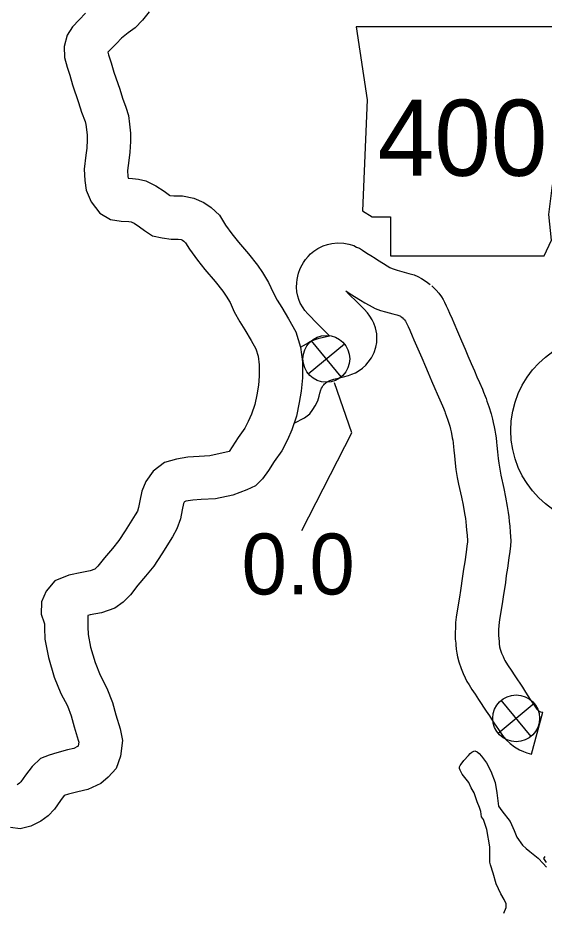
# Model space of a CAD drawing. Extents: x -939622 to -934245, y 1383184 to 1385301.
# Drawn here: x -936319.11 to -936308.16, y 1384751.56 to 1384770.09 of the extents above; entities that cross this region are included whole.
import ezdxf

# ---------------------------------------------------------------- set-up
doc = ezdxf.new("R2010")
doc.units = 0
for name, color, linetype in [('Level 10', 7, 'Continuous'), ('Level 15', 7, 'Continuous'), ('Level 21', 7, 'Continuous'), ('Level 25', 7, 'Continuous'), ('Level 26', 7, 'Continuous'), ('Level 27', 7, 'Continuous'), ('Level 9', 7, 'Continuous')]:
    doc.layers.add(name, color=color, linetype=linetype)

msp = doc.modelspace()

# ---------------------------------------------------------------- linework, layer by layer
at = {"layer": 'Level 10'}
for points in [[(-936313.228, 1384763.232), (-936313.105, 1384763.305), (-936313.025, 1384763.348), (-936312.943, 1384763.383), (-936312.839, 1384763.419), (-936312.753, 1384763.441), (-936312.656, 1384763.465), (-936312.629, 1384763.471), (-936312.683, 1384763.525), (-936312.867, 1384763.711), (-936313.078, 1384763.924), (-936313.137, 1384763.996), (-936313.176, 1384764.049), (-936313.234, 1384764.146), (-936313.263, 1384764.222), (-936313.285, 1384764.295), (-936313.305, 1384764.386), (-936313.31, 1384764.483), (-936313.309, 1384764.569), (-936313.299, 1384764.642), (-936313.287, 1384764.709), (-936313.269, 1384764.775), (-936313.238, 1384764.87), (-936313.196, 1384764.948), (-936313.168, 1384764.995), (-936313.128, 1384765.055), (-936313.073, 1384765.122), (-936313.023, 1384765.172), (-936312.952, 1384765.229), (-936312.869, 1384765.287), (-936312.761, 1384765.34), (-936312.671, 1384765.371), (-936312.575, 1384765.391), (-936312.461, 1384765.401), (-936312.331, 1384765.395), (-936312.223, 1384765.375), (-936312.122, 1384765.346), (-936312.061, 1384765.317), (-936312.004, 1384765.29), (-936311.937, 1384765.249), (-936311.848, 1384765.192), (-936311.764, 1384765.138), (-936311.678, 1384765.084), (-936311.625, 1384765.05), (-936311.504, 1384764.974), (-936311.423, 1384764.924), (-936311.373, 1384764.894), (-936311.319, 1384764.867), (-936311.279, 1384764.853), (-936311.216, 1384764.834), (-936311.073, 1384764.796), (-936310.974, 1384764.769), (-936310.867, 1384764.735), (-936310.788, 1384764.702), (-936310.714, 1384764.665), (-936310.653, 1384764.628), (-936310.584, 1384764.58), (-936310.53, 1384764.537)], [(-936310.5, 1384764.51), (-936310.457, 1384764.469), (-936310.409, 1384764.419), (-936310.353, 1384764.355), (-936310.299, 1384764.278), (-936310.263, 1384764.222), (-936310.234, 1384764.17), (-936310.195, 1384764.091), (-936310.165, 1384764.025), (-936310.129, 1384763.941), (-936310.077, 1384763.82), (-936310.042, 1384763.737), (-936309.964, 1384763.556), (-936309.882, 1384763.368), (-936309.804, 1384763.189), (-936309.745, 1384763.052), (-936309.678, 1384762.892), (-936309.609, 1384762.738), (-936309.557, 1384762.619), (-936309.505, 1384762.495), (-936309.445, 1384762.359), (-936309.422, 1384762.3), (-936309.386, 1384762.215), (-936309.369, 1384762.162), (-936309.35, 1384762.109), (-936309.313, 1384762.001), (-936309.262, 1384761.849), (-936309.233, 1384761.738), (-936309.218, 1384761.667), (-936309.197, 1384761.577), (-936309.184, 1384761.504), (-936309.17, 1384761.424), (-936309.161, 1384761.344), (-936309.152, 1384761.258), (-936309.144, 1384761.186), (-936309.13, 1384761.055), (-936309.118, 1384760.914), (-936309.106, 1384760.822), (-936309.084, 1384760.692), (-936309.058, 1384760.571), (-936308.999, 1384760.295), (-936308.961, 1384760.111), (-936308.928, 1384759.92), (-936308.909, 1384759.796), (-936308.897, 1384759.706), (-936308.886, 1384759.607), (-936308.876, 1384759.509), (-936308.864, 1384759.383), (-936308.855, 1384759.203), (-936308.86, 1384759.102), (-936308.875, 1384758.979), (-936308.893, 1384758.847), (-936308.922, 1384758.632), (-936308.947, 1384758.479), (-936308.967, 1384758.336), (-936309.014, 1384758.035), (-936309.035, 1384757.889), (-936309.082, 1384757.609), (-936309.097, 1384757.509), (-936309.104, 1384757.435), (-936309.108, 1384757.357), (-936309.112, 1384757.275), (-936309.111, 1384757.226), (-936309.105, 1384757.179), (-936309.098, 1384757.105), (-936309.094, 1384757.041), (-936309.092, 1384757.023), (-936309.087, 1384757.001), (-936309.072, 1384756.947), (-936309.045, 1384756.865), (-936309.015, 1384756.794), (-936308.991, 1384756.738), (-936308.979, 1384756.714), (-936308.959, 1384756.682), (-936308.91, 1384756.604), (-936308.847, 1384756.511), (-936308.771, 1384756.396), (-936308.613, 1384756.157), (-936308.547, 1384756.056), (-936308.497, 1384755.981), (-936308.45, 1384755.905), (-936308.367, 1384755.781), (-936308.312, 1384755.702), (-936308.301, 1384755.689), (-936308.281, 1384755.67), (-936308.273, 1384755.664), (-936308.262, 1384755.657), (-936308.256, 1384755.655), (-936308.252, 1384755.653), (-936308.234, 1384755.648), (-936308.185, 1384755.635)], [(-936313.362, 1384761.654), (-936313.148, 1384761.763), (-936313.037, 1384761.848), (-936312.974, 1384761.934), (-936312.922, 1384762.011), (-936312.872, 1384762.118), (-936312.844, 1384762.216), (-936312.826, 1384762.279), (-936312.804, 1384762.348), (-936312.801, 1384762.356), (-936312.79, 1384762.379), (-936312.774, 1384762.41), (-936312.771, 1384762.414), (-936312.763, 1384762.427), (-936312.747, 1384762.449), (-936312.73, 1384762.467), (-936312.712, 1384762.485), (-936312.701, 1384762.495), (-936312.698, 1384762.497), (-936312.676, 1384762.513), (-936312.662, 1384762.522), (-936312.635, 1384762.536), (-936312.619, 1384762.543), (-936312.58, 1384762.556), (-936312.533, 1384762.568), (-936312.445, 1384762.59), (-936312.337, 1384762.615), (-936312.233, 1384762.643), (-936312.161, 1384762.669), (-936312.086, 1384762.701), (-936312.008, 1384762.748), (-936311.94, 1384762.799), (-936311.872, 1384762.861), (-936311.819, 1384762.919), (-936311.749, 1384763.01), (-936311.694, 1384763.122), (-936311.66, 1384763.233), (-936311.644, 1384763.33), (-936311.64, 1384763.409), (-936311.644, 1384763.512), (-936311.67, 1384763.637), (-936311.707, 1384763.73), (-936311.741, 1384763.8), (-936311.787, 1384763.878), (-936311.837, 1384763.946), (-936311.908, 1384764.024), (-936312.046, 1384764.161), (-936312.228, 1384764.344), (-936312.287, 1384764.404), (-936312.247, 1384764.379), (-936312.16, 1384764.324), (-936312.104, 1384764.288), (-936311.98, 1384764.211), (-936311.892, 1384764.156), (-936311.804, 1384764.104), (-936311.675, 1384764.039), (-936311.563, 1384763.998), (-936311.459, 1384763.968), (-936311.306, 1384763.927), (-936311.228, 1384763.906), (-936311.18, 1384763.89), (-936311.164, 1384763.884), (-936311.147, 1384763.875), (-936311.145, 1384763.874), (-936311.123, 1384763.858), (-936311.092, 1384763.834)], [(-936311.122, 1384763.86), (-936311.094, 1384763.833), (-936311.075, 1384763.814), (-936311.063, 1384763.8), (-936311.046, 1384763.776), (-936311.036, 1384763.759), (-936311.029, 1384763.748), (-936311.007, 1384763.703), (-936310.989, 1384763.664), (-936310.957, 1384763.588), (-936310.905, 1384763.467), (-936310.869, 1384763.383), (-936310.79, 1384763.198), (-936310.707, 1384763.009), (-936310.631, 1384762.834), (-936310.574, 1384762.701), (-936310.504, 1384762.533), (-936310.431, 1384762.372), (-936310.384, 1384762.265), (-936310.332, 1384762.14), (-936310.277, 1384762.014), (-936310.256, 1384761.961), (-936310.229, 1384761.897), (-936310.219, 1384761.866), (-936310.199, 1384761.812), (-936310.166, 1384761.715), (-936310.125, 1384761.592), (-936310.108, 1384761.528), (-936310.096, 1384761.471), (-936310.079, 1384761.398), (-936310.071, 1384761.349), (-936310.061, 1384761.295), (-936310.055, 1384761.243), (-936310.046, 1384761.16), (-936310.039, 1384761.09), (-936310.026, 1384760.971), (-936310.013, 1384760.818), (-936309.996, 1384760.686), (-936309.968, 1384760.523), (-936309.939, 1384760.385), (-936309.88, 1384760.11), (-936309.846, 1384759.942), (-936309.816, 1384759.773), (-936309.799, 1384759.667), (-936309.79, 1384759.596), (-936309.781, 1384759.514), (-936309.772, 1384759.423), (-936309.762, 1384759.318), (-936309.756, 1384759.202), (-936309.757, 1384759.18), (-936309.768, 1384759.093), (-936309.785, 1384758.967), (-936309.812, 1384758.765), (-936309.837, 1384758.613), (-936309.857, 1384758.467), (-936309.903, 1384758.171), (-936309.924, 1384758.03), (-936309.971, 1384757.748), (-936309.99, 1384757.618), (-936310.001, 1384757.502), (-936310.007, 1384757.402), (-936310.012, 1384757.288), (-936310.01, 1384757.16), (-936309.999, 1384757.077), (-936309.995, 1384757.039), (-936309.991, 1384756.952), (-936309.978, 1384756.865), (-936309.963, 1384756.791), (-936309.934, 1384756.685), (-936309.888, 1384756.548), (-936309.844, 1384756.443), (-936309.805, 1384756.354), (-936309.765, 1384756.274), (-936309.723, 1384756.206), (-936309.662, 1384756.109), (-936309.594, 1384756.01), (-936309.523, 1384755.901), (-936309.364, 1384755.662), (-936309.298, 1384755.561), (-936309.254, 1384755.494), (-936309.207, 1384755.418), (-936309.111, 1384755.275), (-936309.029, 1384755.156), (-936308.957, 1384755.07), (-936308.864, 1384754.983), (-936308.776, 1384754.915), (-936308.673, 1384754.855), (-936308.589, 1384754.818), (-936308.522, 1384754.794), (-936308.474, 1384754.781), (-936308.422, 1384754.767), (-936308.185, 1384755.635)]]:
    msp.add_lwpolyline(points, dxfattribs=at)
at = {"layer": 'Level 15'}
for points in [[(-936317.706, 1384770.181), (-936317.838, 1384770.043), (-936317.975, 1384769.902), (-936318.088, 1384769.722), (-936318.147, 1384769.487), (-936318.138, 1384769.263), (-936318.088, 1384769.059), (-936318.03, 1384768.89), (-936317.976, 1384768.69), (-936317.847, 1384768.325), (-936317.788, 1384768.124), (-936317.713, 1384767.932), (-936317.694, 1384767.866), (-936317.679, 1384767.759), (-936317.667, 1384767.646), (-936317.67, 1384767.55), (-936317.678, 1384767.373), (-936317.698, 1384767.23), (-936317.729, 1384766.94), (-936317.718, 1384766.699), (-936317.69, 1384766.499), (-936317.585, 1384766.254), (-936317.405, 1384766.02), (-936317.182, 1384765.89), (-936316.958, 1384765.852), (-936316.802, 1384765.845), (-936316.75, 1384765.839), (-936316.741, 1384765.837), (-936316.688, 1384765.811), (-936316.582, 1384765.739), (-936316.473, 1384765.659), (-936316.307, 1384765.548), (-936316.11, 1384765.505), (-936315.919, 1384765.483), (-936315.774, 1384765.482), (-936315.714, 1384765.471), (-936315.682, 1384765.458), (-936315.656, 1384765.439), (-936315.621, 1384765.407), (-936315.541, 1384765.27), (-936315.371, 1384765.044), (-936315.219, 1384764.849), (-936315.008, 1384764.602), (-936314.847, 1384764.398), (-936314.775, 1384764.296), (-936314.694, 1384764.162), (-936314.608, 1384763.967), (-936314.492, 1384763.759), (-936314.39, 1384763.592), (-936314.257, 1384763.37), (-936314.16, 1384763.196), (-936314.111, 1384763.043), (-936314.089, 1384762.868), (-936314.088, 1384762.631), (-936314.106, 1384762.44), (-936314.141, 1384762.244), (-936314.181, 1384762.037), (-936314.252, 1384761.839), (-936314.316, 1384761.686), (-936314.389, 1384761.546), (-936314.525, 1384761.352), (-936314.711, 1384761.06)], [(-936316.381, 1384770.213), (-936316.519, 1384770.035), (-936316.673, 1384769.877), (-936316.817, 1384769.772), (-936316.952, 1384769.663), (-936317.06, 1384769.554), (-936317.189, 1384769.419), (-936317.237, 1384769.369), (-936317.223, 1384769.313), (-936317.169, 1384769.153), (-936317.116, 1384768.958), (-936316.99, 1384768.601), (-936316.935, 1384768.414), (-936316.861, 1384768.224), (-936316.811, 1384768.056), (-936316.786, 1384767.87), (-936316.765, 1384767.683), (-936316.77, 1384767.515), (-936316.781, 1384767.29), (-936316.804, 1384767.12), (-936316.827, 1384766.912), (-936316.821, 1384766.781), (-936316.816, 1384766.747), (-936316.724, 1384766.742), (-936316.602, 1384766.727), (-936316.449, 1384766.695), (-936316.237, 1384766.592), (-936316.064, 1384766.476), (-936315.956, 1384766.396), (-936315.95, 1384766.392), (-936315.867, 1384766.383), (-936315.688, 1384766.382), (-936315.448, 1384766.337), (-936315.239, 1384766.246), (-936315.09, 1384766.141), (-936314.913, 1384765.978), (-936314.791, 1384765.77), (-936314.656, 1384765.591), (-936314.521, 1384765.418), (-936314.312, 1384765.173), (-936314.126, 1384764.938), (-936314.021, 1384764.79), (-936313.894, 1384764.578), (-936313.801, 1384764.368), (-936313.714, 1384764.212), (-936313.62, 1384764.058), (-936313.478, 1384763.821), (-936313.329, 1384763.555), (-936313.228, 1384763.236), (-936313.189, 1384762.925), (-936313.188, 1384762.592), (-936313.213, 1384762.321), (-936313.256, 1384762.079), (-936313.311, 1384761.798), (-936313.413, 1384761.514), (-936313.5, 1384761.304), (-936313.619, 1384761.076), (-936313.777, 1384760.852), (-936313.894, 1384760.668), (-936314.018, 1384760.491), (-936314.169, 1384760.35)], [(-936314.711, 1384761.06), (-936315.116, 1384760.971), (-936315.34, 1384760.96), (-936315.571, 1384760.947), (-936315.811, 1384760.906), (-936316.059, 1384760.835), (-936316.296, 1384760.656), (-936316.448, 1384760.438), (-936316.528, 1384760.238), (-936316.57, 1384760.033), (-936316.598, 1384759.899), (-936316.624, 1384759.824), (-936316.669, 1384759.744), (-936316.877, 1384759.412), (-936317.007, 1384759.208), (-936317.144, 1384759.043), (-936317.306, 1384758.852), (-936317.446, 1384758.676), (-936317.509, 1384758.612), (-936317.509, 1384758.611), (-936317.605, 1384758.578), (-936317.78, 1384758.545), (-936318.051, 1384758.491), (-936318.338, 1384758.371), (-936318.525, 1384758.155), (-936318.618, 1384757.934), (-936318.623, 1384757.676), (-936318.562, 1384757.496), (-936318.555, 1384757.474), (-936318.554, 1384757.392), (-936318.547, 1384757.155), (-936318.475, 1384756.776), (-936318.352, 1384756.368), (-936318.213, 1384756.03), (-936318.081, 1384755.77), (-936318.001, 1384755.559), (-936317.938, 1384755.331), (-936317.854, 1384755.057), (-936317.843, 1384755.012), (-936317.854, 1384754.936), (-936317.855, 1384754.933), (-936317.856, 1384754.932), (-936317.869, 1384754.921), (-936317.949, 1384754.884), (-936318.08, 1384754.852), (-936318.303, 1384754.795), (-936318.459, 1384754.746), (-936318.638, 1384754.677), (-936318.813, 1384754.509), (-936318.954, 1384754.326), (-936319.048, 1384754.187), (-936319.074, 1384754.161), (-936319.105, 1384754.138), (-936319.124, 1384754.128)], [(-936314.169, 1384760.35), (-936314.346, 1384760.266), (-936314.637, 1384760.155), (-936314.997, 1384760.075), (-936315.293, 1384760.061), (-936315.469, 1384760.051), (-936315.612, 1384760.027), (-936315.643, 1384760.018), (-936315.651, 1384760.006), (-936315.663, 1384759.977), (-936315.689, 1384759.851), (-936315.728, 1384759.66), (-936315.8, 1384759.452), (-936315.896, 1384759.284), (-936316.116, 1384758.932), (-936316.279, 1384758.676), (-936316.454, 1384758.465), (-936316.611, 1384758.28), (-936316.77, 1384758.08), (-936316.921, 1384757.926), (-936317.092, 1384757.804), (-936317.372, 1384757.706), (-936317.609, 1384757.661), (-936317.658, 1384757.652), (-936317.654, 1384757.411), (-936317.65, 1384757.253), (-936317.6, 1384756.991), (-936317.503, 1384756.67), (-936317.395, 1384756.406), (-936317.256, 1384756.135), (-936317.144, 1384755.838), (-936317.074, 1384755.582), (-936316.983, 1384755.289), (-936316.93, 1384755.052), (-936316.974, 1384754.726), (-936317.065, 1384754.464), (-936317.229, 1384754.283), (-936317.382, 1384754.154), (-936317.653, 1384754.03), (-936317.862, 1384753.979), (-936318.057, 1384753.929), (-936318.145, 1384753.901), (-936318.224, 1384753.799), (-936318.347, 1384753.617), (-936318.481, 1384753.479), (-936318.633, 1384753.368), (-936318.84, 1384753.263), (-936319.064, 1384753.208), (-936319.267, 1384753.237)]]:
    msp.add_lwpolyline(points, dxfattribs=at)
at = {"layer": 'Level 21'}
msp.add_lwpolyline([(-936312.069, 1384769.902), (-936311.84, 1384768.38), (-936311.942, 1384766.07), (-936311.739, 1384765.943), (-936311.358, 1384765.943), (-936311.358, 1384765.131), (-936308.161, 1384765.131), (-936308.008, 1384765.461), (-936308.059, 1384765.994), (-936307.983, 1384766.603), (-936307.704, 1384767.085), (-936307.526, 1384767.441), (-936307.273, 1384767.821), (-936307.12, 1384768.227), (-936306.993, 1384768.557), (-936306.765, 1384768.836), (-936306.714, 1384769.014), (-936306.816, 1384769.141), (-936307.602, 1384769.141), (-936307.425, 1384769.496), (-936307.399, 1384769.725), (-936307.505, 1384769.9)], close=True, dxfattribs=at)
at = {"layer": 'Level 25'}
msp.add_lwpolyline([(-936313.201, 1384759.417), (-936312.163, 1384761.449), (-936312.524, 1384762.488)], dxfattribs=at)
at = {"layer": 'Level 26'}
for p, q in [((-936313.069, 1384762.68), (-936312.316, 1384763.303)), ((-936312.381, 1384762.615), (-936313.004, 1384763.368)), ((-936309.118, 1384755.199), (-936308.365, 1384755.822)), ((-936308.43, 1384755.134), (-936309.053, 1384755.887))]:
    msp.add_line(p, q, dxfattribs=at)
for centre in [(-936312.692, 1384762.991), (-936308.742, 1384755.51)]:
    msp.add_circle(centre, 0.488, dxfattribs=at)
at = {"layer": 'Level 27'}
msp.add_circle((-936306.873, 1384761.5), 1.98, dxfattribs=at)
at = {"layer": 'Level 9'}
for points in [[(-936308.997, 1384751.459), (-936308.951, 1384751.574), (-936308.951, 1384751.649), (-936308.991, 1384751.741), (-936309.06, 1384751.856), (-936309.158, 1384752.068), (-936309.221, 1384752.287), (-936309.278, 1384752.459), (-936309.29, 1384752.517), (-936309.29, 1384752.833), (-936309.353, 1384753.195), (-936309.422, 1384753.402), (-936309.462, 1384753.459), (-936309.479, 1384753.574), (-936309.502, 1384753.655), (-936309.554, 1384753.775), (-936309.617, 1384753.959), (-936309.675, 1384754.063), (-936309.726, 1384754.177), (-936309.864, 1384754.35), (-936309.91, 1384754.431), (-936309.92, 1384754.463), (-936309.918, 1384754.499), (-936309.905, 1384754.531), (-936309.888, 1384754.554), (-936309.833, 1384754.633), (-936309.737, 1384754.737), (-936309.701, 1384754.778), (-936309.661, 1384754.805), (-936309.622, 1384754.827), (-936309.599, 1384754.837), (-936309.55, 1384754.814), (-936309.512, 1384754.778), (-936309.463, 1384754.722), (-936309.357, 1384754.586), (-936309.267, 1384754.413), (-936309.181, 1384754.177), (-936309.141, 1384753.959)], [(-936309.141, 1384753.959), (-936309.112, 1384753.683), (-936309.043, 1384753.586), (-936308.865, 1384753.361), (-936308.785, 1384753.178), (-936308.727, 1384753.034), (-936308.612, 1384752.873), (-936308.532, 1384752.804), (-936308.457, 1384752.741), (-936308.285, 1384752.603), (-936308.182, 1384752.488), (-936308.113, 1384752.413)], [(-936308.113, 1384752.511), (-936308.164, 1384752.591), (-936308.141, 1384752.637)]]:
    msp.add_lwpolyline(points, dxfattribs=at)

# ---------------------------------------------------------------- texts
at = {"layer": 'Level 21'}
msp.add_text('400', height=1.584, dxfattribs=at).set_placement((-936311.625, 1384766.799))
at = {"layer": 'Level 25'}
msp.add_text('0.0', height=1.2672, dxfattribs=at).set_placement((-936314.456, 1384758.088))

doc.saveas('drawing.dxf')
